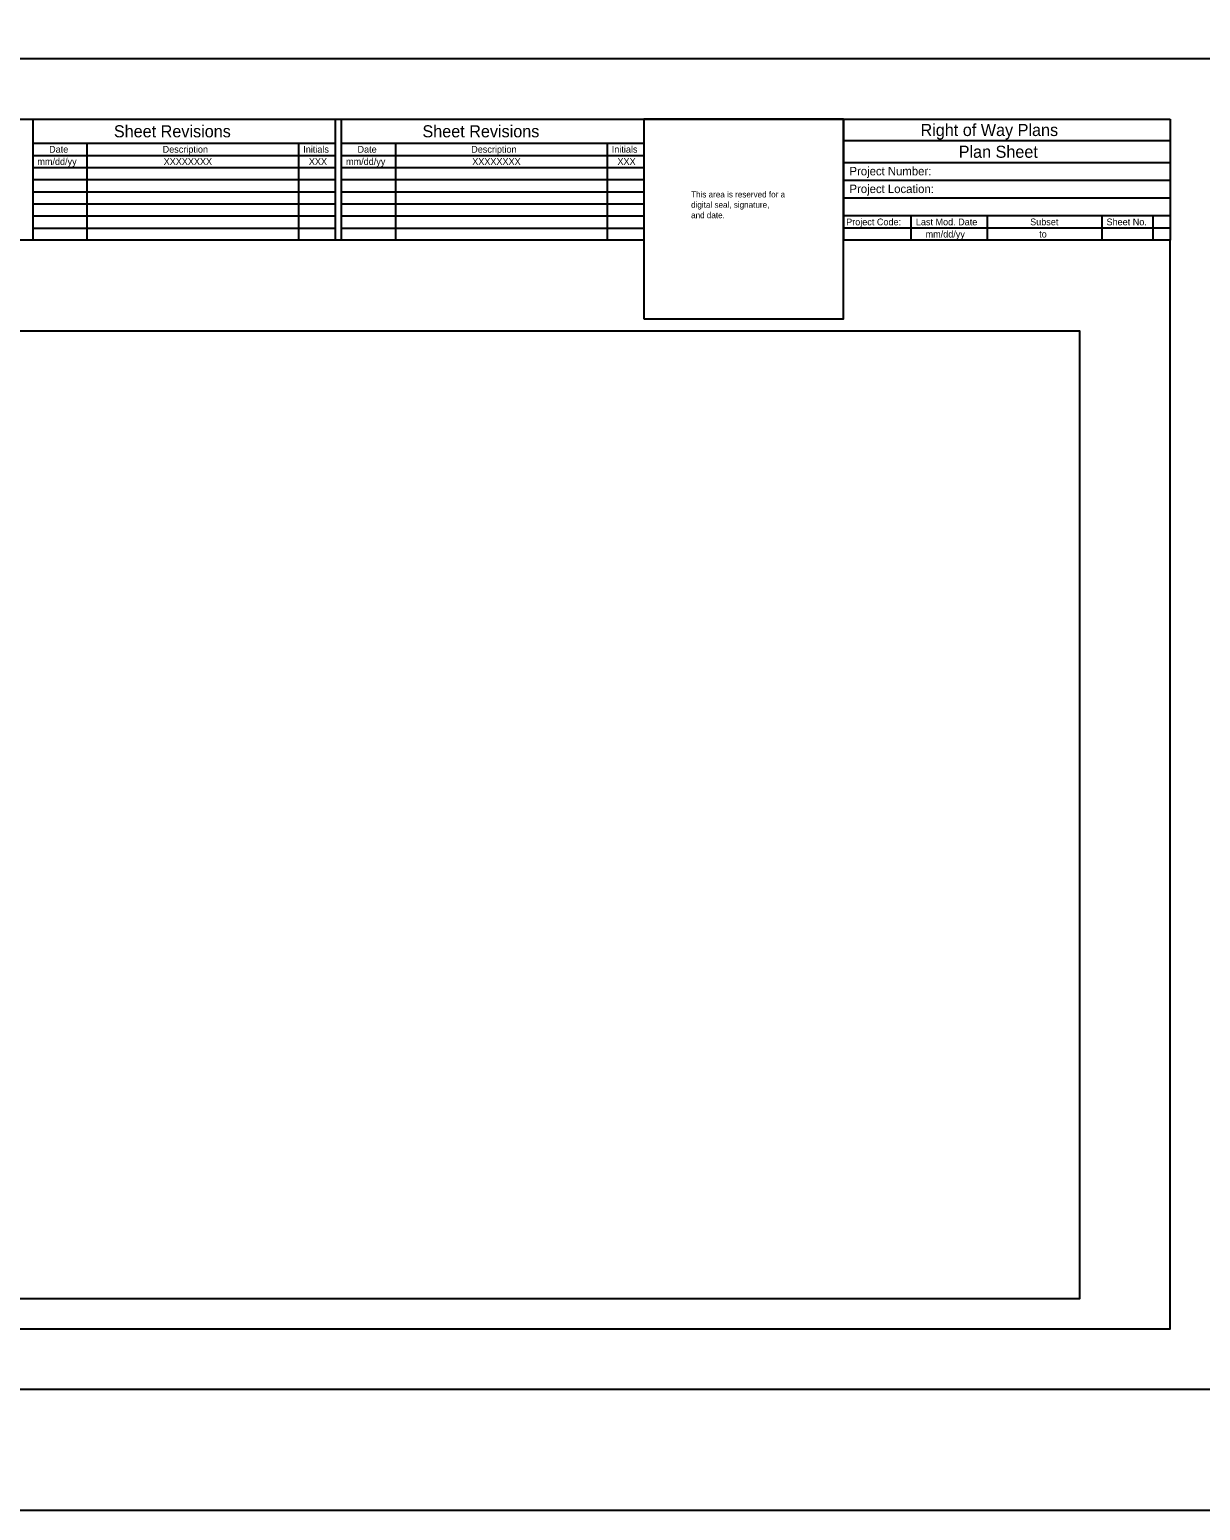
# Model space of a CAD drawing. Extents: x 0 to 3, y 0 to 2.
# Drawn here: x 0.715 to 1.521, y 0 to 1.02 of the extents above; entities that cross this region are included whole.
import ezdxf

# ---------------------------------------------------------------- set-up
doc = ezdxf.new("R2010")
doc.units = 0
for name, color, linetype in [('DRAFT_Information-No Plot', 7, 'Continuous'), ('SHEET_Lines', 7, 'Continuous'), ('SHEET_North Arrow', 7, 'Continuous'), ('SHEET_Plot Boundary', 7, 'Continuous'), ('SHEET_Text-Border Info', 7, 'Continuous')]:
    doc.layers.add(name, color=color, linetype=linetype)

msp = doc.modelspace()

# ---------------------------------------------------------------- linework, layer by layer
at = {"layer": 'DRAFT_Information-No Plot'}
msp.add_lwpolyline([(0.2708, 0.8125), (1.4375, 0.8125), (1.4375, 0.1458), (0.2708, 0.1458)], close=True, dxfattribs=at)
at = {"layer": 'SHEET_Lines'}
for p, q in [((0.125, 1), (2.9583, 1)), ((0.2083, 0.9583), (1.5, 0.9583)), ((0.7167, 0.9583), (0.7167, 0.875)), ((0.925, 0.9583), (0.925, 0.875)), ((0.9292, 0.9583), (0.9292, 0.875)), ((1.1375, 0.9583), (1.1375, 0.875)), ((1.275, 0.9583), (1.275, 0.875)), ((1.5, 0.9583), (1.5, 0.875)), ((0.7167, 0.9417), (0.925, 0.9417)), ((0.7542, 0.875), (0.7542, 0.9417)), ((0.9, 0.875), (0.9, 0.9417)), ((0.9292, 0.9417), (1.1375, 0.9417)), ((0.9667, 0.875), (0.9667, 0.9417)), ((1.1125, 0.875), (1.1125, 0.9417)), ((1.5, 0.9433), (1.275, 0.9433)), ((0.7167, 0.9333), (0.925, 0.9333)), ((0.9292, 0.9333), (1.1375, 0.9333)), ((1.5, 0.9283), (1.275, 0.9283)), ((0.7167, 0.925), (0.925, 0.925)), ((0.9292, 0.925), (1.1375, 0.925)), ((0.7167, 0.9167), (0.925, 0.9167)), ((0.7167, 0.9083), (0.925, 0.9083)), ((0.9292, 0.9167), (1.1375, 0.9167)), ((0.9292, 0.9083), (1.1375, 0.9083)), ((1.5, 0.9161), (1.275, 0.9161)), ((0.7167, 0.9), (0.925, 0.9)), ((0.9292, 0.9), (1.1375, 0.9)), ((1.5, 0.9039), (1.275, 0.9039)), ((0.7167, 0.8917), (0.925, 0.8917)), ((0.9292, 0.8917), (1.1375, 0.8917)), ((1.5, 0.8917), (1.275, 0.8917)), ((1.3217, 0.875), (1.3217, 0.8917)), ((1.3742, 0.875), (1.3742, 0.8917)), ((1.4533, 0.875), (1.4533, 0.8917)), ((1.4883, 0.875), (1.4883, 0.8917)), ((0.7167, 0.8833), (0.925, 0.8833)), ((0.9292, 0.8833), (1.1375, 0.8833)), ((1.5, 0.8833), (1.275, 0.8833))]:
    msp.add_line(p, q, dxfattribs=at)
for points in [[(2.9583, 0.0833), (0.125, 0.0833), (0.125, 1.9167), (2.9583, 1.9167)], [(1.1375, 0.8208), (1.275, 0.8208), (1.275, 0.9583), (1.1375, 0.9583)]]:
    msp.add_lwpolyline(points, close=True, dxfattribs=at)
msp.add_lwpolyline([(1.1375, 0.875), (0.2083, 0.875), (0.2083, 0.125), (1.5, 0.125), (1.5, 0.875), (1.275, 0.875)], dxfattribs=at)
at = {"layer": 'SHEET_Plot Boundary'}
msp.add_lwpolyline([(0, 2), (3, 2), (3, 0), (0, 0)], close=True, dxfattribs=at)

# ---------------------------------------------------------------- texts
at = {"layer": 'DRAFT_Information-No Plot'}
for s, height, p in [('This area is reserved for a', 0.004167, (1.1701, 0.9044)), ('digital seal, signature,', 0.004167, (1.1701, 0.8973)), ('and date.', 0.00417, (1.1701, 0.8901))]:
    msp.add_text(s, height=height, dxfattribs=at).set_placement(p)
at = {"layer": 'SHEET_North Arrow'}
for s, height, p in [('Sheet Revisions', 0.008333, (0.7726, 0.9458)), ('Sheet Revisions', 0.008333, (0.9851, 0.9458)), ('Right of Way Plans', 0.008333, (1.3281, 0.9467)), ('Plan Sheet', 0.00833, (1.3544, 0.9317))]:
    msp.add_text(s, height=height, dxfattribs=at).set_placement(p)
at = {"layer": 'SHEET_Text-Border Info'}
for s, height, p in [('Date', 0.00467, (0.728, 0.9352)), ('Description', 0.004667, (0.8062, 0.9352)), ('Initials', 0.00467, (0.903, 0.9352)), ('Date', 0.00467, (0.9404, 0.9352)), ('Description', 0.004667, (1.0187, 0.9352)), ('Initials', 0.00467, (1.1155, 0.9352)), ('mm/dd/yy', 0.00467, (0.7199, 0.9268)), ('XXXXXXXX', 0.00467, (0.8069, 0.9268)), ('XXX', 0.00467, (0.9069, 0.9268)), ('mm/dd/yy', 0.00467, (0.9325, 0.9268)), ('XXXXXXXX', 0.00467, (1.0194, 0.9268)), ('XXX', 0.00467, (1.1194, 0.9268)), ('Project Number:', 0.005833, (1.2792, 0.9196)), ('Project Location:', 0.005833, (1.2792, 0.9074)), ('Project Code:', 0.004667, (1.2769, 0.8852)), ('Last Mod. Date', 0.004667, (1.3249, 0.8852)), ('Subset', 0.00467, (1.4036, 0.8852)), ('Sheet No.', 0.00467, (1.4562, 0.8852)), ('mm/dd/yy', 0.00467, (1.3316, 0.8768)), (' to ', 0.00467, (1.4081, 0.8768))]:
    msp.add_text(s, height=height, dxfattribs=at).set_placement(p)

doc.saveas('drawing.dxf')
